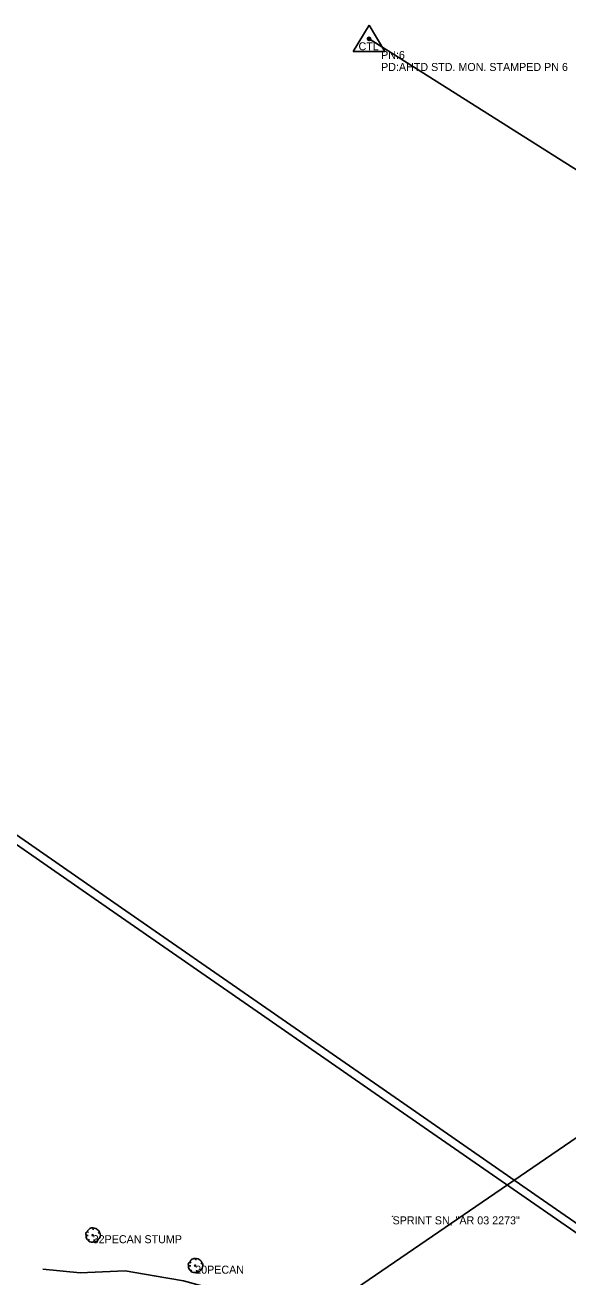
# Model space of a CAD drawing. Extents: x 997398 to 1003416, y 334596 to 337085.
# Drawn here: x 999019 to 999358, y 336058 to 336841 of the extents above; entities that cross this region are included whole.
import ezdxf

# ---------------------------------------------------------------- set-up
doc = ezdxf.new("R2010")
doc.units = 0
for name, color, linetype in [('Default', 7, 'Continuous'), ('S_FIBER_OPTIC_CABLE_ANNOT', 7, 'Continuous'), ('S_MSC_PT_SYM', 7, 'Continuous'), ('S_PRIMARY_CTL', 7, 'Continuous'), ('S_PRIMARY_CTL_ANNOT', 7, 'Continuous'), ('S_RAILROAD', 7, 'Continuous'), ('S_STREAM', 7, 'Continuous'), ('S_TREE', 7, 'Continuous'), ('S_TREE_ANNOT', 7, 'Continuous'), ('S_UTL_PT_SYM', 7, 'Continuous')]:
    doc.layers.add(name, color=color, linetype=linetype)

msp = doc.modelspace()

# ---------------------------------------------------------------- linework, layer by layer
at = {"layer": 'Default'}
for p, q in [((999737.12, 336514.03), (999233.93, 336831.87)), ((998964.3, 335872.43), (999557.02, 336277.74))]:
    msp.add_line(p, q, dxfattribs=at)
at = {"layer": 'S_MSC_PT_SYM'}
for points in [[(999079.25, 336282.97), (999079.25, 336283.02), (999079.25, 336282.97), (999079.2, 336282.97), (999079.25, 336282.97), (999079.25, 336282.92), (999079.25, 336282.97), (999079.3, 336282.97)], [(999081.98, 336287.15), (999081.98, 336287.2), (999081.98, 336287.15), (999081.93, 336287.15), (999081.98, 336287.15), (999081.98, 336287.1), (999081.98, 336287.15), (999082.03, 336287.15)], [(999166.74, 336228.39), (999166.74, 336228.44), (999166.74, 336228.39), (999166.69, 336228.39), (999166.74, 336228.39), (999166.74, 336228.34), (999166.74, 336228.39), (999166.79, 336228.39)], [(999163.96, 336224.27), (999163.96, 336224.32), (999163.96, 336224.27), (999163.91, 336224.27), (999163.96, 336224.27), (999163.96, 336224.22), (999163.96, 336224.27), (999164.01, 336224.27)], [(999252.9, 336168.56), (999252.9, 336168.61), (999252.9, 336168.56), (999252.85, 336168.56), (999252.9, 336168.56), (999252.9, 336168.51), (999252.9, 336168.56), (999252.95, 336168.56)], [(999250.01, 336164.45), (999250.01, 336164.5), (999250.01, 336164.45), (999249.96, 336164.45), (999250.01, 336164.45), (999250.01, 336164.4), (999250.01, 336164.45), (999250.06, 336164.45)], [(999337.53, 336103.75), (999337.53, 336103.8), (999337.53, 336103.75), (999337.48, 336103.75), (999337.53, 336103.75), (999337.53, 336103.7), (999337.53, 336103.75), (999337.58, 336103.75)], [(999340.2, 336107.93), (999340.2, 336107.98), (999340.2, 336107.93), (999340.15, 336107.93), (999340.2, 336107.93), (999340.2, 336107.88), (999340.2, 336107.93), (999340.25, 336107.93)]]:
    msp.add_lwpolyline(points, dxfattribs=at)
at = {"layer": 'S_PRIMARY_CTL'}
for p, q in [((999233.93, 336840.57), (999223.9, 336824.05)), ((999233.93, 336840.57), (999243.76, 336824.05)), ((999223.9, 336824.05), (999243.76, 336824.05))]:
    msp.add_line(p, q, dxfattribs=at)
for radius in [1.04, 0.609, 0.344]:
    msp.add_circle((999233.93, 336831.87), radius, dxfattribs=at)
at = {"layer": 'S_RAILROAD'}
for p, q in [((998997.03, 336340), (999079.25, 336282.97)), ((999081.98, 336287.15), (998999.95, 336344.09)), ((999079.25, 336282.97), (999163.96, 336224.27)), ((999166.74, 336228.39), (999081.98, 336287.15)), ((999252.9, 336168.56), (999166.74, 336228.39)), ((999163.96, 336224.27), (999250.01, 336164.45)), ((999340.2, 336107.93), (999252.9, 336168.56)), ((999250.01, 336164.45), (999337.53, 336103.75)), ((999337.53, 336103.75), (999424.31, 336043.62)), ((999425.68, 336048.66), (999340.2, 336107.93))]:
    msp.add_line(p, q, dxfattribs=at)
at = {"layer": 'S_STREAM'}
msp.add_lwpolyline([(999030.13, 336063.09), (999053.42, 336060.79), (999067.52, 336061.49), (999081.61, 336062.19), (999099.8, 336059.05), (999117.99, 336055.9), (999137.08, 336050.73), (999156.18, 336045.56), (999166.41, 336030.96), (999176.64, 336016.36), (999183.48, 336004.74), (999190.31, 335993.12), (999199.28, 335979.3), (999208.26, 335965.48), (999220.04, 335959.33), (999231.82, 335953.19), (999242.01, 335943.09), (999252.2, 335933)], dxfattribs=at)
at = {"layer": 'S_TREE'}
for p, q in [((999061.91, 336088.64), (999061.52, 336087.79)), ((999057.46, 336084.3), (999058.58, 336084.3)), ((999058.11, 336086.62), (999058.62, 336086.04)), ((999058.62, 336081.12), (999059.08, 336081.82)), ((999062.3, 336080.85), (999062.22, 336081.63)), ((999064.7, 336081.74), (999064.24, 336082.17)), ((999065.48, 336085.85), (999064.82, 336085.58)), ((999121.46, 336065.25), (999122.59, 336065.25)), ((999122.12, 336067.58), (999122.62, 336067)), ((999125.92, 336069.59), (999125.53, 336068.74)), ((999129.48, 336066.8), (999128.82, 336066.53)), ((999122.62, 336062.07), (999123.09, 336062.77)), ((999126.31, 336061.8), (999126.23, 336062.58)), ((999128.71, 336062.69), (999128.24, 336063.12))]:
    msp.add_line(p, q, dxfattribs=at)
for centre in [(999061.35, 336084.39), (999125.36, 336065.35)]:
    msp.add_circle(centre, 0.341, dxfattribs=at)
for centre, major_axis, ratio, start_param, end_param in [((999060.02, 336087.6), (1.86, 1.08), 0.471018, 0, 3.141593), ((999063.67, 336087.27), (-1.81, 1.36), 0.405113, 3.141593, 6.283186), ((999057.78, 336085.48), (0.31, 1.03), 0.646762, 0, 3.141593), ((999058.09, 336082.83), (-0.61, 1.6), 0.420543, 6.283185, 9.424777), ((999060.55, 336081.05), (-1.83, 0.19), 0.529943, 0, 3.141593), ((999063.51, 336081.34), (1.09, 0.46), 0.711534, 3.141592, 6.283185), ((999065.03, 336083.86), (0.46, 2.04), 0.482994, 3.141593, 6.283185), ((999121.79, 336066.43), (0.31, 1.03), 0.646762, 0, 3.141593), ((999122.09, 336063.78), (-0.61, 1.6), 0.420543, 6.283185, 9.424777), ((999124.02, 336068.55), (1.86, 1.08), 0.471018, 0, 3.141593), ((999127.68, 336068.23), (-1.81, 1.36), 0.405113, 3.141593, 6.283186), ((999129.03, 336064.82), (0.46, 2.04), 0.482994, 3.141593, 6.283185), ((999124.56, 336062), (-1.83, 0.19), 0.529943, 0, 3.141593), ((999127.51, 336062.3), (1.09, 0.46), 0.711534, 3.141592, 6.283185)]:
    msp.add_ellipse(centre, major_axis=major_axis, ratio=ratio, start_param=start_param, end_param=end_param, dxfattribs=at)
at = {"layer": 'S_UTL_PT_SYM'}
msp.add_lwpolyline([(999248.61, 336096.16), (999248.61, 336096.21), (999248.61, 336096.16), (999248.56, 336096.16), (999248.61, 336096.16), (999248.61, 336096.11), (999248.61, 336096.16), (999248.66, 336096.16)], dxfattribs=at)

# ---------------------------------------------------------------- texts
at = {"layer": 'S_FIBER_OPTIC_CABLE_ANNOT'}
msp.add_text('SPRINT SN, "AR 03 2273"', height=5, dxfattribs=at).set_placement((999248.61, 336091.16))
at = {"layer": 'S_PRIMARY_CTL'}
msp.add_text('CTL', height=5, rotation=360, dxfattribs=at).set_placement((999227.35, 336824.79))
at = {"layer": 'S_PRIMARY_CTL_ANNOT'}
for s, p in [('PN:6', (999241.43, 336819.37)), ('PD:AHTD STD. MON. STAMPED PN 6', (999241.43, 336811.87))]:
    msp.add_text(s, height=5, dxfattribs=at).set_placement(p)
at = {"layer": 'S_TREE_ANNOT'}
for s, p in [('32PECAN STUMP', (999061.35, 336079.39)), ('20PECAN', (999125.36, 336060.35))]:
    msp.add_text(s, height=5, dxfattribs=at).set_placement(p)

doc.saveas('drawing.dxf')
